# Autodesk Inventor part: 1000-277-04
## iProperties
Created: 2007-03
Part Number: 1000-277-04
Document SubType Name: Modeling
Designer: Andy Moles
Material: Steel
Density: 7.85 g/cm^3
Mass: 7.1882 g
Surface Area: 8.7918 cm^2
Volume: 0.915695 cm^3
Author: Andy Moles
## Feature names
1. Base1
